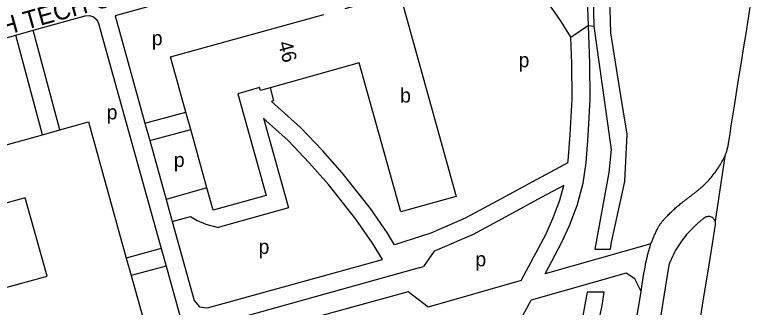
# Model space of a CAD drawing. Extents: x 158358 to 160383, y 379531 to 380764.
# Drawn here: x 160128 to 160335.4, y 380396.2 to 380477.3 of the extents above; entities that cross this region are included whole.
import ezdxf

# ---------------------------------------------------------------- set-up
doc = ezdxf.new("R2010")
doc.units = 0
for name, color, linetype in [('BLT_Basislijn', 7, 'Continuous'), ('BLT_Bebouwing', 7, 'Continuous'), ('BLT_Centroide', 7, 'Continuous'), ('BLT_Huisnummer', 7, 'Continuous'), ('BLT_Straatnaam', 7, 'Continuous'), ('BLT_Vlakafsluiter', 7, 'Continuous')]:
    doc.layers.add(name, color=color, linetype=linetype)

msp = doc.modelspace()

# ---------------------------------------------------------------- linework, layer by layer
at = {"layer": 'BLT_Basislijn'}
for p, q in [((160288.5, 380483.09), (160288.71, 380474.23)), ((160293.39, 380472.38), (160293.09, 380483.09)), ((160140.46, 380445.4), (160133.02, 380473.07)), ((160288.71, 380474.23), (160290.21, 380463.66)), ((160135.64, 380444.06), (160128.21, 380471.73)), ((160295.97, 380456.61), (160293.39, 380472.38)), ((160290.21, 380463.66), (160292.45, 380447.81)), ((160298, 380444.22), (160295.97, 380456.61)), ((160164.09, 380447.31), (160175.48, 380450.31)), ((160292.45, 380447.81), (160293.56, 380439.94)), ((160165.43, 380442.49), (160176.81, 380445.49)), ((160297.36, 380431.09), (160298, 380444.22)), ((160293.56, 380439.94), (160292.88, 380433.55)), ((160292.88, 380433.55), (160289.02, 380412.27)), ((160181.31, 380429.27), (160170, 380426.07)), ((160293.62, 380414.22), (160297.36, 380431.09)), ((160304.57, 380413.77), (160275.19, 380405.42)), ((160293.34, 380412.27), (160293.62, 380414.22)), ((160168.6, 380412.41), (160158.91, 380409.8)), ((160289.02, 380412.27), (160293.34, 380412.27)), ((160169.94, 380407.59), (160160.25, 380404.99)), ((160240.21, 380407.06), (160241.46, 380407.48)), ((160268.51, 380403.52), (160242.74, 380396.2)), ((160286.85, 380400.36), (160285.14, 380390.94)), ((160291.6, 380400.29), (160286.85, 380400.36)), ((160291.06, 380396.6), (160291.6, 380400.29)), ((160287.96, 380382.4), (160291.06, 380396.6))]:
    msp.add_line(p, q, dxfattribs=at)
for points in [[(160287.24, 380474.39), (160286.67, 380489.31), (160286.88, 380498.28), (160288.03, 380510.75), (160290.58, 380526.4), (160294.67, 380542.71), (160296.53, 380552.81), (160297.48, 380562.97), (160297.53, 380573.71), (160296.74, 380583.36), (160296.02, 380588.46)], [(160230.27, 380500.21), (160241.45, 380499.58), (160247.84, 380498.61), (160251.85, 380497.52), (160256.26, 380495.82), (160261.04, 380493.54), (160264.37, 380491.6), (160267.44, 380489.13), (160270.76, 380486.35), (160273.96, 380483.04), (160277.01, 380479.09), (160279.37, 380475.83), (160282.35, 380471.05)], [(160326, 380441.03), (160326.43, 380443.79), (160326.86, 380446.54), (160327.3, 380449.3), (160327.73, 380452.05), (160328.22, 380455.18), (160328.91, 380459.43), (160329.6, 380463.69), (160330.28, 380467.94), (160330.97, 380472.2), (160331.65, 380476.45), (160332.33, 380480.7), (160333.01, 380484.94), (160333.69, 380489.19), (160334.37, 380493.44), (160334.68, 380495.37), (160334.86, 380496.52), (160335.05, 380497.68), (160335.23, 380498.84), (160335.41, 380500)], [(160209.76, 380492.06), (160155.8, 380477.13)], [(160133.02, 380473.07), (160147.51, 380477.1), (160148.68, 380477.21), (160149.79, 380476.82), (160150.58, 380476.18), (160150.96, 380475.65), (160151.2, 380475.01), (160168.6, 380412.41)], [(160155.8, 380477.13), (160164.09, 380447.31)], [(160128.21, 380471.73), (160133.02, 380473.07)], [(160275.19, 380405.42), (160279.86, 380414.18), (160281.97, 380418.84), (160284.05, 380424.37), (160285.73, 380430.64), (160286.55, 380436.27), (160287.16, 380443.73), (160287.74, 380453.91), (160287.61, 380463.99), (160287.24, 380474.39)], [(160104.8, 380465.23), (160128.21, 380471.73)], [(160281.5, 380436.26), (160281.58, 380436.83), (160282.17, 380444.08), (160282.74, 380454.01), (160282.61, 380463.87), (160282.35, 380471.05)], [(160198.81, 380457.13), (160199.82, 380453.5), (160199.23, 380453.34)], [(160233.4, 380413.46), (160231.43, 380416.7), (160226.69, 380423.54), (160218.89, 380433.45), (160213.4, 380439.67), (160207.32, 380446.07), (160201.11, 380451.67), (160199.23, 380453.34)], [(160196.99, 380448.64), (160203.92, 380423.72), (160184.38, 380418.28)], [(160230, 380409.42), (160227.23, 380413.98), (160222.67, 380420.56), (160215.04, 380430.24), (160209.71, 380436.3), (160203.83, 380442.48), (160197.77, 380447.95), (160196.99, 380448.64)], [(160164.09, 380447.31), (160165.43, 380442.49)], [(160165.43, 380442.49), (160170, 380426.07)], [(160325.11, 380438.12), (160325.17, 380438.27), (160325.23, 380438.42), (160325.28, 380438.57), (160325.34, 380438.72), (160325.39, 380438.87), (160325.45, 380439.02), (160325.5, 380439.17), (160325.55, 380439.33), (160325.6, 380439.48), (160325.64, 380439.63), (160325.69, 380439.79), (160325.73, 380439.94), (160325.77, 380440.1), (160325.82, 380440.25), (160325.86, 380440.41), (160325.89, 380440.56), (160325.93, 380440.72), (160325.97, 380440.88), (160326, 380441.03)], [(160320.45, 380431.22), (160320.74, 380431.55), (160321.03, 380431.88), (160321.31, 380432.22), (160321.59, 380432.56), (160321.86, 380432.9), (160322.13, 380433.25), (160322.39, 380433.61), (160322.65, 380433.96), (160322.9, 380434.32), (160323.15, 380434.69), (160323.39, 380435.06), (160323.62, 380435.43), (160323.85, 380435.8), (160324.08, 380436.18), (160324.29, 380436.56), (160324.51, 380436.95), (160324.71, 380437.34), (160324.92, 380437.73), (160325.11, 380438.12)], [(160281.5, 380436.26), (160271.73, 380431), (160261.93, 380425.69), (160252.98, 380420.88), (160243.49, 380416.72), (160233.4, 380413.46)], [(160280.37, 380429.98), (160274.1, 380426.6), (160264.3, 380421.29), (160255.17, 380416.38), (160245.27, 380412.04), (160244.4, 380411.76), (160241.46, 380407.48)], [(160268.51, 380403.52), (160270.03, 380406.37), (160275.37, 380416.39), (160277.34, 380420.76), (160279.28, 380425.9), (160280.37, 380429.98)], [(160316.71, 380427.9), (160316.92, 380428.07), (160317.12, 380428.23), (160317.33, 380428.4), (160317.53, 380428.56), (160317.73, 380428.73), (160317.93, 380428.9), (160318.13, 380429.07), (160318.33, 380429.24), (160318.53, 380429.42), (160318.73, 380429.59), (160318.93, 380429.77), (160319.12, 380429.95), (160319.31, 380430.12), (160319.51, 380430.3), (160319.7, 380430.48), (160319.89, 380430.67), (160320.08, 380430.85), (160320.27, 380431.03), (160320.45, 380431.22)], [(160313.52, 380425.47), (160313.69, 380425.6), (160313.86, 380425.73), (160314.03, 380425.85), (160314.19, 380425.98), (160314.36, 380426.11), (160314.53, 380426.24), (160314.7, 380426.37), (160314.86, 380426.49), (160315.03, 380426.62), (160315.2, 380426.75), (160315.37, 380426.88), (160315.53, 380427.01), (160315.7, 380427.13), (160315.87, 380427.26), (160316.04, 380427.39), (160316.21, 380427.52), (160316.37, 380427.65), (160316.54, 380427.77), (160316.71, 380427.9)], [(160170, 380426.07), (160171.69, 380419.99)], [(160308.75, 380421.12), (160308.98, 380421.37), (160309.22, 380421.62), (160309.45, 380421.86), (160309.69, 380422.1), (160309.93, 380422.35), (160310.17, 380422.58), (160310.42, 380422.82), (160310.66, 380423.05), (160310.91, 380423.29), (160311.16, 380423.52), (160311.42, 380423.74), (160311.67, 380423.97), (160311.93, 380424.19), (160312.19, 380424.41), (160312.45, 380424.63), (160312.72, 380424.84), (160312.98, 380425.05), (160313.25, 380425.26), (160313.52, 380425.47)], [(160171.69, 380419.99), (160176.74, 380421.39), (160178.6, 380420.22), (160180.98, 380419.24), (160184.38, 380418.28)], [(160306.38, 380417.93), (160306.48, 380418.11), (160306.58, 380418.29), (160306.69, 380418.48), (160306.8, 380418.66), (160306.91, 380418.83), (160307.02, 380419.01), (160307.14, 380419.19), (160307.26, 380419.36), (160307.38, 380419.53), (160307.51, 380419.7), (160307.63, 380419.87), (160307.77, 380420.03), (160307.9, 380420.19), (160308.03, 380420.35), (160308.17, 380420.51), (160308.31, 380420.67), (160308.46, 380420.82), (160308.6, 380420.97), (160308.75, 380421.12)], [(160322.39, 380420.06), (160322.28, 380420.3), (160322.14, 380420.52), (160321.98, 380420.71), (160321.8, 380420.88), (160321.6, 380421.03), (160321.39, 380421.14), (160321.16, 380421.23), (160320.92, 380421.3), (160320.67, 380421.33), (160320.41, 380421.33), (160320.16, 380421.29), (160319.91, 380421.23), (160319.67, 380421.13), (160319.46, 380421.01), (160319.27, 380420.86)], [(160171.69, 380419.99), (160177.79, 380398.02), (160179.21, 380396.21), (160181.49, 380395.93), (160230, 380409.42)], [(160305.66, 380313.16), (160305.67, 380313.26), (160305.69, 380313.36), (160305.86, 380314.43), (160306.13, 380316.08), (160306.59, 380318.93), (160307.61, 380325.38), (160308.63, 380331.83), (160309.87, 380339.71), (160311.14, 380347.8), (160312.38, 380355.68), (160313.6, 380363.35), (160314.82, 380371.02), (160316.05, 380378.69), (160317.28, 380386.36), (160318.92, 380396.68), (160320.7, 380407.88), (160321.91, 380415.55), (160322.21, 380417.32), (160322.5, 380419.08)], [(160319.27, 380420.86), (160319.1, 380420.74), (160318.93, 380420.61), (160318.77, 380420.48), (160318.6, 380420.35), (160318.44, 380420.21), (160318.27, 380420.08), (160318.11, 380419.94), (160317.95, 380419.8), (160317.79, 380419.66), (160317.63, 380419.52), (160317.48, 380419.38), (160317.32, 380419.24), (160317.17, 380419.09), (160317.02, 380418.95), (160316.86, 380418.8), (160316.71, 380418.65), (160316.57, 380418.5), (160316.42, 380418.35), (160316.27, 380418.2)], [(160322.5, 380419.08), (160322.52, 380419.32), (160322.51, 380419.57), (160322.46, 380419.82), (160322.39, 380420.06)], [(160304.57, 380413.77), (160304.88, 380414.56), (160304.97, 380414.8), (160305.07, 380415.05), (160305.17, 380415.29), (160305.27, 380415.53), (160305.38, 380415.78), (160305.48, 380416.02), (160305.59, 380416.26), (160305.7, 380416.5), (160305.81, 380416.74), (160305.92, 380416.98), (160306.03, 380417.22), (160306.15, 380417.45), (160306.27, 380417.69), (160306.38, 380417.93)], [(160316.27, 380418.2), (160315.8, 380417.74), (160315.34, 380417.27), (160314.89, 380416.79), (160314.46, 380416.3), (160314.03, 380415.8), (160313.62, 380415.28), (160313.22, 380414.76), (160312.83, 380414.22), (160312.45, 380413.67), (160312.09, 380413.12), (160311.75, 380412.55), (160311.42, 380411.98), (160311.1, 380411.4), (160310.8, 380410.81), (160310.52, 380410.21), (160310.25, 380409.61), (160309.99, 380409.01), (160309.75, 380408.39), (160309.53, 380407.78)], [(160303.03, 380407.95), (160303.09, 380408.21), (160303.15, 380408.47), (160303.21, 380408.73), (160303.27, 380408.99), (160303.33, 380409.25), (160303.39, 380409.51), (160303.45, 380409.77), (160303.51, 380410.03), (160303.57, 380410.29), (160303.65, 380410.58), (160303.73, 380410.88), (160303.82, 380411.19), (160303.9, 380411.49), (160303.99, 380411.8), (160304.07, 380412.1), (160304.16, 380412.41), (160304.24, 380412.71), (160304.33, 380413.02), (160304.57, 380413.77)], [(160168.6, 380412.41), (160169.94, 380407.59)], [(160169.94, 380407.59), (160180.74, 380368.74)], [(160240.21, 380407.06), (160182.83, 380391.11), (160181.02, 380389.7), (160180.74, 380387.42), (160199.27, 380320.75)], [(160309.53, 380407.78), (160307.81, 380396.94), (160306.09, 380386.09), (160304.37, 380375.25), (160302.82, 380365.49), (160301.96, 380360.06), (160301.11, 380354.63), (160300.25, 380349.19), (160299.39, 380343.8), (160298.53, 380338.48), (160297.67, 380333.15), (160296.82, 380327.82), (160296.35, 380324.88), (160296.14, 380323.53), (160295.93, 380322.18), (160295.72, 380320.83), (160295.57, 380319.9), (160295.44, 380319.08), (160295.31, 380318.26), (160295.17, 380317.43)], [(160301.82, 380400.5), (160302.14, 380402.51), (160302.43, 380404.33), (160302.63, 380405.53), (160302.83, 380406.74), (160303.03, 380407.95)], [(160301.82, 380400.5), (160300.14, 380404.05), (160297.65, 380405.57), (160271.27, 380398.07)], [(160242.74, 380396.2), (160237.13, 380400.38), (160190.32, 380387.51), (160187.5, 380382.17), (160202.09, 380329.35), (160208.12, 380325.88), (160252.36, 380338.2)], [(160292.1, 380339.45), (160292.71, 380343.22), (160292.92, 380344.53), (160293.14, 380345.83), (160293.49, 380347.99), (160294.38, 380353.59), (160295.27, 380359.18), (160296.16, 380364.78), (160297.01, 380370.13), (160297.8, 380375.14), (160298.59, 380380.14), (160299.38, 380385.15), (160300.1, 380389.71), (160300.78, 380393.98), (160301.46, 380398.24), (160301.82, 380400.5)], [(160255.96, 380371.05), (160261.44, 380379.86), (160267.16, 380390.37), (160271.27, 380398.07)]]:
    msp.add_lwpolyline(points, dxfattribs=at)
at = {"layer": 'BLT_Bebouwing'}
for points in [[(160219.69, 380479.12), (160234.83, 380483.32), (160250.47, 380426.92), (160235.11, 380422.66), (160223.54, 380464), (160198.81, 380457.13)], [(160175.48, 380450.31), (160171.22, 380465.68), (160213.78, 380477.48)], [(160198.81, 380457.13), (160196.15, 380456.39), (160195.88, 380457.19), (160189.91, 380455.43), (160197.76, 380427.19), (160183.02, 380423.11), (160181.31, 380429.27)], [(160176.81, 380445.49), (160175.48, 380450.31)], [(160140.46, 380445.4), (160148.4, 380447.6), (160158.91, 380409.8)], [(160096.07, 380433.07), (160135.64, 380444.06)], [(160135.64, 380444.06), (160140.46, 380445.4)], [(160181.31, 380429.27), (160176.81, 380445.49)], [(160130.88, 380426.57), (160109.28, 380420.57), (160115.32, 380398.81), (160136.91, 380404.8), (160130.88, 380426.57)], [(160158.91, 380409.8), (160160.25, 380404.99)], [(160160.25, 380404.99), (160171.05, 380366.13)]]:
    msp.add_lwpolyline(points, dxfattribs=at)
at = {"layer": 'BLT_Vlakafsluiter'}
for p, q in [((160287.24, 380474.39), (160282.35, 380471.05)), ((160287.24, 380474.39), (160288.71, 380474.23)), ((160325.11, 380438.12), (160322.39, 380420.06))]:
    msp.add_line(p, q, dxfattribs=at)

# ---------------------------------------------------------------- texts
at = {"layer": 'BLT_Centroide'}
for s, p in [('p', (160166.01, 380468.92)), ('p', (160267.84, 380462.82)), ('b', (160234.94, 380453)), ('p', (160153.48, 380448.33)), ('p', (160172.12, 380435.1)), ('p', (160195.66, 380410.97)), ('p', (160255.85, 380407.52))]:
    msp.add_text(s, height=4, dxfattribs=at).set_placement(p)
at = {"layer": 'BLT_Huisnummer'}
msp.add_text('46', height=4, rotation=285.5331, dxfattribs=at).set_placement((160200.97, 380469.53))
at = {"layer": 'BLT_Straatnaam'}
msp.add_text('HIGH TECH CAMPUS', height=5, rotation=15.534, dxfattribs=at).set_placement((160113.2, 380468.25))

doc.saveas('drawing.dxf')
